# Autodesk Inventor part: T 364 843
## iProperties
Company: Mayer & Müller AG Schaltgeräte
Created: 2005-10
Part Number: T 364 843
Material: 1.0330
Document SubType Name: Sheet Metal
Designer: I.Baliuc
Manufacturer: Standard
Standards Organization: Custom
Description: Seitenblech
Density: 7.84 g/cm^3
Sheet Metal Rule: Standard
Zweck: Schaltrohr Trenner
Author: T.Messerschmitt
Revision Number: 364843
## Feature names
1. Bohrung1 [Hole]
2. Grobblech1
